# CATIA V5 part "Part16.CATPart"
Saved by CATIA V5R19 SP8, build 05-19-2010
Part number: Plaque_b
Bounding box of the stored display mesh (mm): x 729.928 to 1525.198, y -176.114 to 619.989, z 0 to 12
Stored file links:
  G:\EU_thinkMotion\CFAO_2010\MMS_groupe1\MMS_groupe1\OK\ppiault\piault\piault_cfao\Part16.CATPart
  D:\Catia\Finaltest.CATProduct
  G:\EU_thinkMotion\CFAO_2010\MMS_groupe1\MMS_groupe1\OK\ppiault\piault\piault_cfao\Part12.CATPart
  G:\Catia Projet\CFAO2\Product2.CATProduct
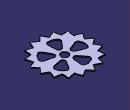
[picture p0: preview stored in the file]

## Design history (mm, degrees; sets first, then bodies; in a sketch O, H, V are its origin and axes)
External parameters (linked from other documents)
  External.DiametreRabatteur = 400 mm
  External.Epaisseur = 5 mm
Body1 (main body)
  Sketch1 on xy-plane, origin (0, 0, 0), H (1, 0, 0), V (0, 1, 0)
    point P1 (1520.0725, 133.4859)
    line L1 (1457.4541, 208.3407) -> (1520.0725, 133.4859)
    point P4 (1129.6852, 220.651)
    arc A1 centre (1129.6852, 220.651) radius 328 from (1457.4541, 208.3407) to (1431.5615, 92.375) ccw
    line L2 (1520.0725, 133.4859) -> (1431.5615, 92.375)
    circle A2 centre (1129.6852, 220.651) radius 52
    radius A1 = 328 {= External.DiametreRabatteur *0.82}
    radius A2 = 52
    distance P4 P1 = 400 {= External.DiametreRabatteur}
    angle L1 L2 = 75
  Pad1: profile Sketch1, direction (0, 0, 1), length 12 {= 2.4*External.Epaisseur}
  CircPattern1: of Pad1, instances 18, angular step 21.1765, axis from end face of Pad1
  Sketch2 on face of CircPattern1, origin (0, 0, 0), H (1, 0, 0), V (0, -1, 0)
    arc A1 centre (1232.019, -148.8679) radius 35 from (1201.8521, -131.1208) to (1240.8011, -182.7482) ccw
    point P1 (1232.019, -148.8679)
    arc A2 centre (1290.3308, -49.7482) radius 35 from (1308.0779, -19.5813) to (1260.1639, -32.0011) ccw
    arc A3 centre (1343.3399, -120.0124) radius 35 from (1352.122, -153.8927) to (1377.2202, -111.2302) ccw
    arc A4 centre (1232.019, -148.8679) radius 150 from (1377.2202, -111.2302) to (1308.0779, -19.5813) ccw
    point P4 (1232.019, -148.8679)
    line L1 (1201.8521, -131.1208) -> (1260.1639, -32.0011)
    point P5 (1201.8521, -131.1208)
    line L2 (1240.8011, -182.7482) -> (1352.122, -153.8927)
    point P11 (1201.8521, -131.1208)
    reference projected point E1 (1129.6852, -220.651) from axis of face of CircPattern1
    reference projected point E2 (1129.6852, -220.651) from axis of face of CircPattern1
    radius A1 = 35
    radius A2 = 35
    radius A3 = 35
    angle L2 L1 = 45
    distance P4 E1 = 125 {= 125/400*External.DiametreRabatteur}
    distance E2 A4 = 275 {= 275/400*External.DiametreRabatteur}
    coincidence: P1 P4, P5 A1, L1 P11, P5 P11
    tangency: L2 A1, L2 A3, L1 A1, L1 A2
  Pocket1: profile Sketch2, direction (0, 0, 1), length 12 {= 2.4*External.Epaisseur}
  CircPattern2: of Pocket1, instances 6, angular step 72, axis from face of CircPattern1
